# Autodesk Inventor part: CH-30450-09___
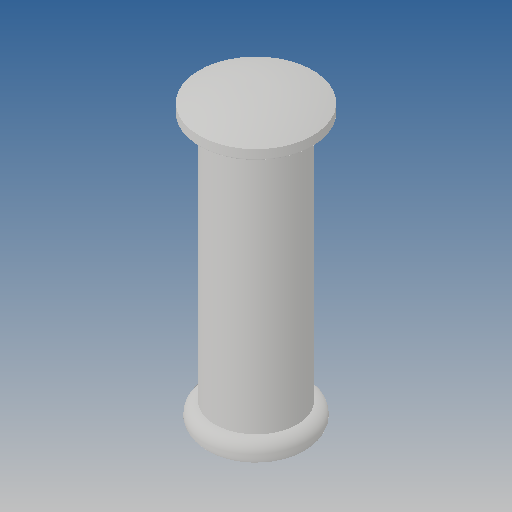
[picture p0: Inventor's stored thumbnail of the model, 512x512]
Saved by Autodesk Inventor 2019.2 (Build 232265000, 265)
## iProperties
Created: 2010-06
Part Number: CH-30450-09___
Material: Ogólny
Document SubType Name: Modeling
Designer: CADENGINEERING4
Density: 1 g/cm^3
Appearance: Domyślna
Author: CADENGINEERING4
Revision Number: ANY
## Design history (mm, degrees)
feature "NONE"
node "Bryła1"
